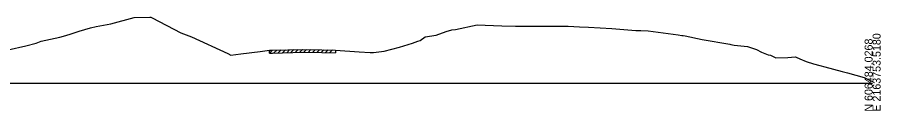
# Model space of a CAD drawing. Extents: x -26 to 6803, y -10 to 19606.
# Drawn here: x 6500.9 to 6802.8, y 3990.3 to 4023.1 of the extents above; entities that cross this region are included whole.
import ezdxf

# ---------------------------------------------------------------- set-up
doc = ezdxf.new("R2010")
doc.units = 0
for name, color, linetype in [('RD_GPK_XS_Cell', 7, 'Continuous'), ('RD_XS_ExGround', 7, 'Continuous'), ('RD_XS_ExPaveRet', 7, 'Continuous')]:
    doc.layers.add(name, color=color, linetype=linetype)

msp = doc.modelspace()

# ---------------------------------------------------------------- linework, layer by layer
at = {"layer": 'RD_GPK_XS_Cell'}
msp.add_line((6400, 4000), (6800, 4000), dxfattribs=at)
at = {"layer": 'RD_XS_ExGround'}
msp.add_lwpolyline([(6497.65, 4011.64), (6503.84, 4013.03), (6507.45, 4013.96), (6509.28, 4014.67), (6515.71, 4016.09), (6517, 4016.41), (6519.41, 4017.17), (6520.43, 4017.49), (6522.55, 4018.19), (6526.44, 4019.43), (6528.48, 4019.8), (6532.32, 4020.5), (6533.54, 4020.82), (6541.8, 4022.99), (6547.23, 4023.09), (6547.62, 4023.11), (6548.04, 4022.89), (6558.06, 4017.62), (6561.84, 4016.27), (6574.47, 4010.36), (6575.58, 4009.84), (6579.07, 4010.27), (6585.86, 4011.12), (6589.1, 4011.53), (6590.16, 4011.56), (6600.76, 4011.82), (6607.35, 4011.69), (6612.19, 4011.6), (6620.47, 4011.02), (6624.34, 4010.77), (6624.99, 4010.73), (6625.44, 4010.79), (6629.21, 4011.24), (6634.55, 4012.62), (6639.12, 4014.07), (6640.95, 4014.66), (6641.79, 4014.97), (6643.53, 4016.24), (6647.39, 4016.84), (6650.84, 4018.15), (6652.8, 4018.65), (6654.11, 4018.86), (6661.65, 4020.43), (6664.51, 4020.33), (6670.32, 4020.07), (6675.06, 4019.96), (6676.04, 4019.95), (6676.52, 4019.96), (6693.52, 4019.93), (6697.48, 4019.73), (6700.6, 4019.57), (6708.76, 4019.1), (6713.03, 4018.77), (6717.19, 4018.47), (6718.98, 4018.47), (6721.48, 4018.28), (6732.01, 4016.93), (6733.31, 4016.74), (6733.71, 4016.68), (6734.4, 4016.56), (6740.4, 4015.33), (6750.05, 4013.62), (6750.44, 4013.51), (6751.53, 4013.3), (6756.26, 4012.89), (6759.38, 4011.84), (6761.12, 4010.82), (6762.88, 4010.14), (6763.46, 4009.95), (6764.3, 4009.85), (6766.12, 4008.88), (6770.36, 4009.04), (6772.92, 4009.27), (6773.25, 4009.12), (6774.59, 4008.57), (6776.76, 4007.56), (6779.31, 4006.76), (6781.5, 4006.23), (6783.28, 4005.69), (6789.3, 4004.06), (6791.23, 4003.57), (6797.1, 4001.94), (6799.39, 4000.81), (6800, 4000.52)], dxfattribs=at)
at = {"layer": 'RD_XS_ExPaveRet'}
for p, q in [((6589.1, 4010.53), (6590.13, 4011.56)), ((6589.1, 4010.53), (6589.1, 4011.53)), ((6589.1, 4010.53), (6590.16, 4010.56)), ((6590.16, 4010.56), (6600.76, 4010.82)), ((6590.6, 4010.57), (6591.63, 4011.59)), ((6592.1, 4010.61), (6593.13, 4011.63)), ((6593.6, 4010.64), (6594.63, 4011.67)), ((6595.1, 4010.68), (6596.13, 4011.71)), ((6596.6, 4010.72), (6597.63, 4011.74)), ((6598.1, 4010.76), (6599.13, 4011.78)), ((6599.6, 4010.79), (6600.63, 4011.82)), ((6600.76, 4010.82), (6607.35, 4010.69)), ((6601.1, 4010.81), (6602.08, 4011.79)), ((6602.6, 4010.78), (6603.58, 4011.76)), ((6604.1, 4010.75), (6605.08, 4011.73)), ((6605.6, 4010.72), (6606.58, 4011.7)), ((6607.1, 4010.69), (6608.08, 4011.68)), ((6607.35, 4010.69), (6612.19, 4010.6)), ((6608.6, 4010.67), (6609.58, 4011.65)), ((6610.1, 4010.64), (6611.08, 4011.62)), ((6612.19, 4011.6), (6612.19, 4010.6)), ((6612.19, 4010.6), (6612.19, 4010.6))]:
    msp.add_line(p, q, dxfattribs=at)

# ---------------------------------------------------------------- texts
at = {"layer": 'RD_GPK_XS_Cell'}
for s, p in [('E 2163753.5180', (6802.8, 3990)), ('N 606484.0268', (6800, 3990))]:
    msp.add_text(s, height=2.8, rotation=90, dxfattribs=at).set_placement(p)

doc.saveas('drawing.dxf')
